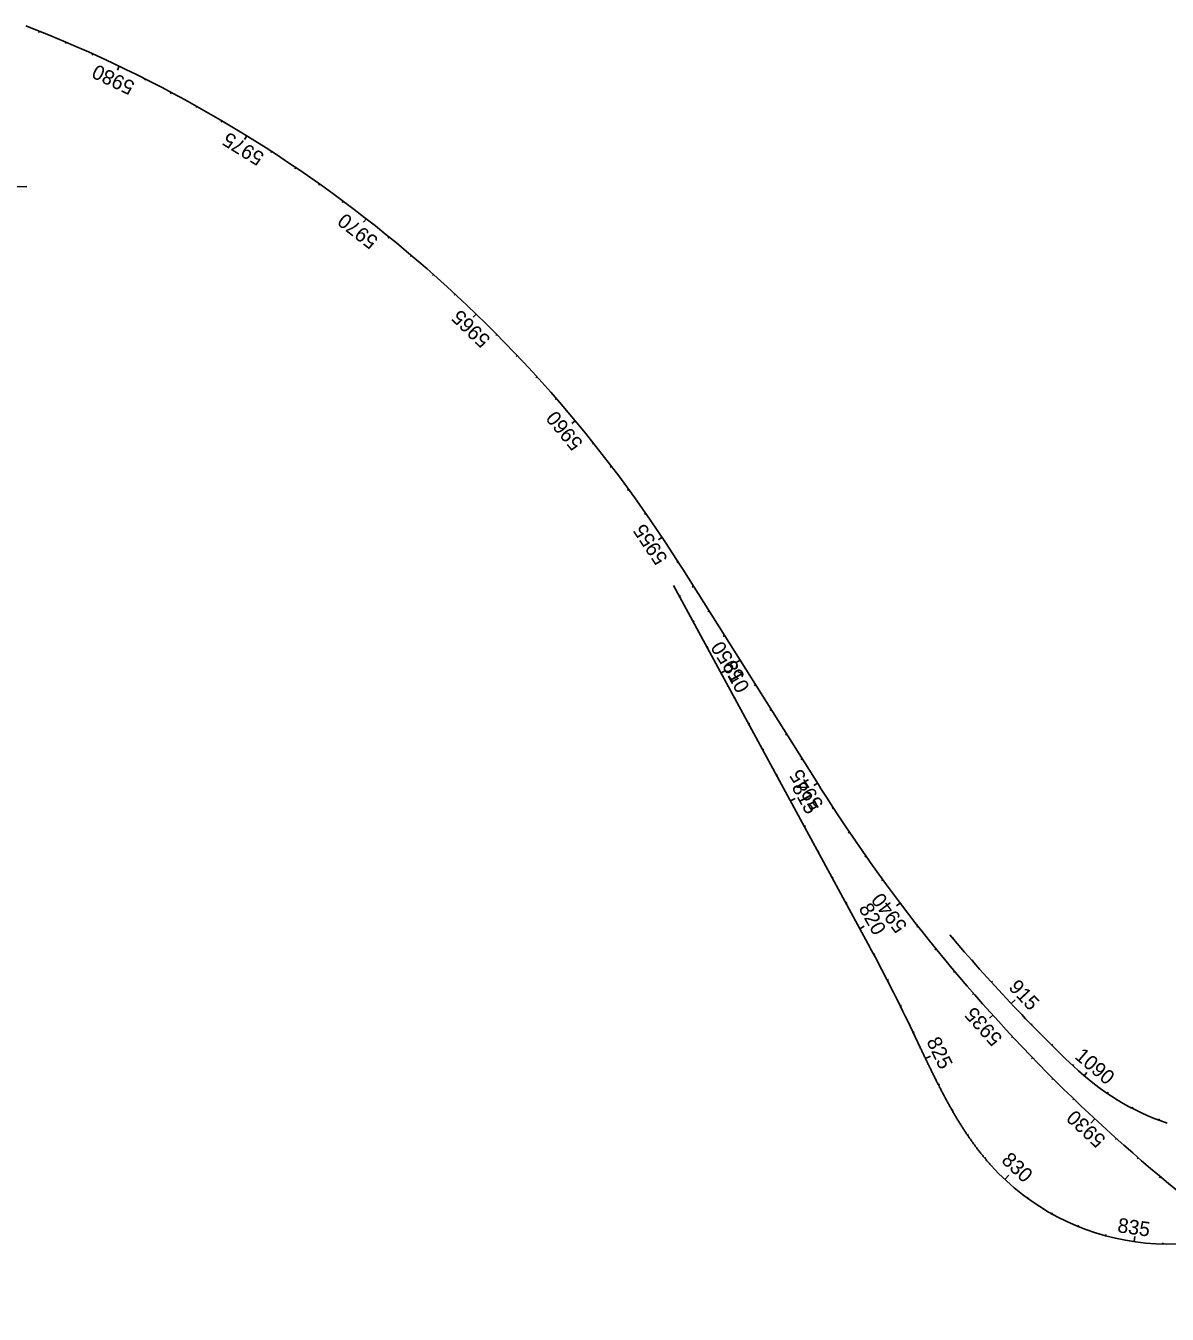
# Model space of a CAD drawing. Extents: x 448091 to 665917, y 1461380 to 1587607.
# Drawn here: x 482144 to 486066, y 1527133 to 1531560 of the extents above; entities that cross this region are included whole.
import ezdxf

# ---------------------------------------------------------------- set-up
doc = ezdxf.new("R2010")
doc.units = 0
for name, color, linetype in [('BoxCulvert_ep', 7, 'Continuous'), ('TextShtNo', 7, 'Continuous'), ('TextTitle', 7, 'Continuous')]:
    doc.layers.add(name, color=color, linetype=linetype)

msp = doc.modelspace()

# ---------------------------------------------------------------- linework, layer by layer
at = {"layer": 'BoxCulvert_ep'}
msp.add_line((477221.1, 1530966.4), (482148.1, 1531007.3), dxfattribs=at)
at = {"layer": 'TextShtNo'}
for p, q in [((484401.6, 1529692.6), (484392.9, 1529706.4)), ((484873.3, 1528943.9), (484401.6, 1529692.6)), ((485045.9, 1528391.1), (484369.6, 1529636.5)), ((485217.7, 1528049), (485182.7, 1528122.6))]:
    msp.add_line(p, q, dxfattribs=at)
for centre, radius, start, end in [((480462.7, 1527229.1), 4645.6, 32.2243, 68.783), ((489720.3, 1531999.2), 5729.6, 212.22426, 238.14093), ((489699.4, 1532130.3), 5729.6, 220.1469, 226.3589), ((480010.7, 1525657), 5729.6, 25.4878, 28.5017), ((486353.1, 1528622.4), 881.5, 226.3291, 251.0258), ((486068.8, 1528192.4), 818.5, 222.1128, 302.2473)]:
    msp.add_arc(centre, radius, start, end, dxfattribs=at)
msp.add_spline([(485217.7, 1528049), (485220.5, 1528043.2), (485223.2, 1528037.4), (485226, 1528031.7), (485228.8, 1528025.9), (485231.5, 1528020.1), (485234.3, 1528014.3), (485237.1, 1528008.5), (485239.9, 1528002.7), (485242.7, 1527996.9), (485245.4, 1527991.1), (485248.2, 1527985.4), (485251, 1527979.6), (485253.9, 1527973.8), (485256.7, 1527968.1), (485259.5, 1527962.3), (485262.3, 1527956.5), (485265.2, 1527950.8), (485268, 1527945), (485270.9, 1527939.3), (485273.8, 1527933.5), (485276.7, 1527927.8), (485279.6, 1527922.1), (485282.5, 1527916.4), (485285.4, 1527910.7), (485288.4, 1527905), (485291.3, 1527899.3), (485294.3, 1527893.6), (485297.3, 1527887.9), (485300.3, 1527882.2), (485303.3, 1527876.6), (485306.4, 1527870.9), (485309.4, 1527865.3), (485312.5, 1527859.6), (485315.6, 1527854), (485318.7, 1527848.4), (485321.9, 1527842.8), (485325, 1527837.2), (485328.2, 1527831.7), (485331.4, 1527826.1), (485334.7, 1527820.6), (485337.9, 1527815), (485341.2, 1527809.5), (485344.5, 1527804), (485347.8, 1527798.5), (485351.2, 1527793), (485354.6, 1527787.6), (485358, 1527782.1), (485361.4, 1527776.7), (485364.9, 1527771.3), (485368.4, 1527765.9), (485371.9, 1527760.6), (485375.4, 1527755.2), (485379, 1527749.9), (485382.6, 1527744.6), (485386.2, 1527739.3), (485389.9, 1527734), (485393.6, 1527728.8), (485397.3, 1527723.5), (485401.1, 1527718.3), (485404.9, 1527713.2), (485408.7, 1527708), (485412.6, 1527702.9), (485416.5, 1527697.8), (485420.4, 1527692.7), (485424.4, 1527687.6), (485428.4, 1527682.6), (485432.4, 1527677.6), (485436.5, 1527672.7), (485440.6, 1527667.7), (485444.7, 1527662.8), (485448.9, 1527657.9), (485453.1, 1527653.1), (485457.3, 1527648.3), (485461.6, 1527643.5)], degree=3, dxfattribs=at)
at = {"layer": 'TextTitle'}
for p, q in [((482190.4, 1531541.5), (482188.6, 1531536.9)), ((482282.8, 1531503.3), (482280.9, 1531498.7)), ((482374.4, 1531463.1), (482372.4, 1531458.6)), ((482465.1, 1531421), (482458.7, 1531407.5)), ((482554.9, 1531376.9), (482552.6, 1531372.5)), ((482643.7, 1531331), (482641.3, 1531326.5)), ((482731.5, 1531283.1), (482729, 1531278.7)), ((482818.2, 1531233.3), (482815.7, 1531229)), ((482903.8, 1531181.7), (482895.9, 1531168.9)), ((482988.3, 1531128.2), (482985.6, 1531124)), ((483071.7, 1531072.9), (483068.9, 1531068.8)), ((483153.8, 1531015.9), (483150.9, 1531011.8)), ((483234.7, 1530957.1), (483231.7, 1530953.1)), ((483314.3, 1530896.6), (483305.1, 1530884.7)), ((483392.6, 1530834.3), (483389.4, 1530830.5)), ((483469.5, 1530770.4), (483466.3, 1530766.6)), ((483545, 1530704.9), (483541.7, 1530701.2)), ((483619.1, 1530637.8), (483615.7, 1530634.1)), ((483691.8, 1530569), (483681.3, 1530558.2)), ((483762.9, 1530498.8), (483759.3, 1530495.2)), ((483832.5, 1530427), (483828.9, 1530423.5)), ((483900.6, 1530353.7), (483896.9, 1530350.3)), ((483967, 1530279), (483963.2, 1530275.7)), ((484031.8, 1530202.8), (484020.3, 1530193.2)), ((484095, 1530125.3), (484091.1, 1530122.2)), ((484156.5, 1530046.5), (484152.5, 1530043.4)), ((484216.3, 1529966.3), (484212.3, 1529963.4)), ((484274.4, 1529884.9), (484270.3, 1529882)), ((484330.6, 1529802.2), (484318.1, 1529793.9)), ((484385.1, 1529718.4), (484380.9, 1529715.7)), ((484389.8, 1529599.4), (484393.5, 1529601.4)), ((484438.5, 1529633.8), (484434.2, 1529631.1)), ((484437.5, 1529511.5), (484441.2, 1529513.6)), ((484491.8, 1529549.2), (484487.6, 1529546.5)), ((484485.2, 1529423.6), (484489, 1529425.7)), ((484545.1, 1529464.6), (484540.9, 1529461.9)), ((484598.4, 1529380), (484585.7, 1529372)), ((484532.9, 1529335.8), (484548.8, 1529344.4)), ((484651.8, 1529295.4), (484647.5, 1529292.7)), ((484580.6, 1529247.9), (484584.4, 1529249.9)), ((484705.1, 1529210.8), (484700.9, 1529208.2)), ((484628.4, 1529160), (484632.1, 1529162)), ((484758.4, 1529126.2), (484754.2, 1529123.6)), ((484676.1, 1529072.1), (484679.8, 1529074.2)), ((484811.7, 1529041.6), (484807.5, 1529039)), ((484723.8, 1528984.2), (484727.6, 1528986.3)), ((484865.1, 1528957), (484852.4, 1528949)), ((484771.5, 1528896.4), (484787.4, 1528905)), ((484918.9, 1528872.8), (484914.7, 1528870)), ((484819.2, 1528808.5), (484823, 1528810.5)), ((484974.2, 1528789.4), (484970.1, 1528786.6)), ((484867, 1528720.6), (484870.7, 1528722.6)), ((485030.9, 1528707.1), (485026.8, 1528704.2)), ((484914.7, 1528632.7), (484918.4, 1528634.8)), ((485089.1, 1528625.8), (485085.1, 1528622.8)), ((484962.4, 1528544.9), (484966.1, 1528547)), ((484962.4, 1528544.8), (484966.1, 1528546.9)), ((485148.7, 1528545.5), (485136.7, 1528536.4)), ((485010.1, 1528457), (485025.5, 1528465.6)), ((485209.7, 1528466.2), (485205.7, 1528463.1)), ((485330.4, 1528423.6), (485333.6, 1528426.4)), ((485057.8, 1528369.1), (485061.5, 1528371.1)), ((485272, 1528388), (485268.1, 1528384.9)), ((485395.7, 1528348), (485398.9, 1528350.8)), ((485104.3, 1528280.6), (485108.1, 1528282.5)), ((485335.7, 1528310.9), (485331.9, 1528307.7)), ((485462.4, 1528273.4), (485465.8, 1528276.6)), ((485400.7, 1528235), (485397, 1528231.7)), ((485149.4, 1528191.3), (485153.2, 1528193.2)), ((485530.3, 1528200.1), (485543.8, 1528212.7)), ((485467.1, 1528160.1), (485456, 1528150.1)), ((485192.8, 1528101.2), (485196.7, 1528103.1)), ((485599.6, 1528127.9), (485602.6, 1528130.9)), ((485534.7, 1528086.5), (485531.1, 1528083.1)), ((485670, 1528057), (485673, 1528060)), ((485235.9, 1528011), (485252.7, 1528019)), ((485600.1, 1528010.6), (485603.7, 1528014)), ((485741.7, 1527987.3), (485744.7, 1527990.3)), ((485780.9, 1527951.8), (485790.7, 1527963.2)), ((485280, 1527921.2), (485283.8, 1527923.2)), ((485673.8, 1527942.8), (485670.3, 1527939.3)), ((485745.2, 1527872.8), (485741.8, 1527869.2)), ((485860.5, 1527891.3), (485863.3, 1527895.5)), ((485327.4, 1527833.2), (485331.1, 1527835.3)), ((485946.4, 1527840.3), (485948.8, 1527844.7)), ((485817.9, 1527804.1), (485804.2, 1527789.4)), ((486037.6, 1527799.3), (486039.4, 1527803.9)), ((485380.1, 1527748.2), (485383.7, 1527750.6)), ((485891.7, 1527736.6), (485888.3, 1527732.9)), ((485440.1, 1527668.3), (485443.4, 1527671)), ((485966.7, 1527670.4), (485963.4, 1527666.6)), ((485508.7, 1527595.6), (485522.6, 1527610.4)), ((486042.8, 1527605.6), (486039.6, 1527601.7)), ((485585.6, 1527531.8), (485588.1, 1527535.2)), ((485669.7, 1527477.8), (485671.8, 1527481.5)), ((485759.8, 1527434.5), (485761.4, 1527438.4)), ((485854.4, 1527402.5), (485855.6, 1527406.6)), ((485952.3, 1527382.2), (485954.8, 1527399.6)), ((486051.9, 1527374.1), (486052, 1527378.3))]:
    msp.add_line(p, q, dxfattribs=at)

# ---------------------------------------------------------------- texts
for s, rotation, p in [('5980', 154.4672, (482522.2, 1531365)), ('5975', 148.3005, (482967.2, 1531118.5)), ('5970', 142.1338, (483358.6, 1530827.8)), ('5965', 135.9672, (483744.2, 1530484.7)), ('5960', 129.8005, (484061.5, 1530127)), ('5955', 123.6338, (484352, 1529729.5)), ('5950', 122.2243, (484616.6, 1529324.8)), ('810', 298.5015, (484536, 1529360.3)), ('5945', 122.2243, (484887.3, 1528885)), ('815', 298.5024, (484774.5, 1528944.2)), ('820', 299.251, (485004.7, 1528527.7)), ('5940', 127.0697, (485175.6, 1528467)), ('915', 313.31, (485518.5, 1528253.6)), ('5935', 132.0697, (485503, 1528082.3)), ('825', 295.6187, (485238.1, 1528070.7)), ('1090', 319.5293, (485745.3, 1528014.2)), ('5930', 137.0697, (485858.5, 1527736.9)), ('830', 316.8156, (485493.6, 1527657.5)), ('835', 351.8159, (485893.2, 1527414.9))]:
    msp.add_text(s, height=50, rotation=rotation, dxfattribs=at).set_placement(p)

doc.saveas('drawing.dxf')
